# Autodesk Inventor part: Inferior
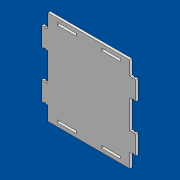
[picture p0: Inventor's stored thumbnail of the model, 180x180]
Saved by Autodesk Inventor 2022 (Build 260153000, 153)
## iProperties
Created: 2022-05
Part Number: Inferior
Material: Generic
Document SubType Name: Modeling
Designer: Daniel
Density: 1 g/cm^3
Appearance: Default
Author: Daniel
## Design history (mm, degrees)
sketch "Sketch1"
  geometry: L1 (60, -95)-(60, 5); L2 (-30, -95)-(-30, 5); L3 (-30, 5)-(-28.5, 5); L4 (60, -95)-(-30, -95); L5 (65, 0)-(65, 2.5); L6 (60, -45)-(49, -45); L7 (-34.1, -10)-(-35, -10); L8 (-35, -10)-(-35, -30); L9 (-34.1, -30)-(-35, -30); L10 (-34.1, -60)-(-35, -60); L11 (-35, -80)-(-35, -60); L12 (-34.1, -80)-(-35, -80); L13 (-30, 5)-(-30, -10); L14 (-30, -30)-(-30, -60); L15 (-30, -80)-(-30, -95); L16 (-35, 5)-(65, -95); L17 (-28.5, -88.5)-(58.5, -88.5); L18 (58.5, -88.5)-(58.5, -1.5); L19 (58.5, -1.5)-(-28.5, -1.5); L20 (-28.5, -1.5)-(-28.5, -88.5); L21 (-28.5, -88.5)-(58.5, -1.5); L22 (58.5, -88.5)-(-28.5, -1.5); L23 (-18.5, -1.5)-(-18.5, 1); L24 (-18.5, 1)-(1.5, 1); L25 (1.5, 1)-(1.5, -1.5); L26 (1.5, -1.5)-(-18.5, -1.5); L27 (28.5, -1.5)-(28.5, 1); L28 (28.5, 1)-(48.5, 1); L29 (48.5, 1)-(48.5, -1.5); L30 (48.5, -1.5)-(28.5, -1.5); L31 (15, -45)-(33.857, -45); L32 (58.5, -88.5)-(-28.5, -88.5); L33 (1.5, -88.5)-(-18.5, -88.5); L34 (-18.5, -88.5)-(-18.5, -91); L35 (-18.5, -91)-(1.5, -91); L36 (1.5, -91)-(1.5, -88.5); L37 (48.5, -88.5)-(28.5, -88.5); L38 (28.5, -88.5)-(28.5, -91); L39 (28.5, -91)-(48.5, -91); L40 (48.5, -91)-(48.5, -88.5); L41 (-28.5, -10)-(-31.8, -10); L42 (-31.8, -10)-(-35, -10); L43 (-35, -30)-(-28.5, -30); L44 (-28.5, -10)-(-28.5, 5); L45 (-28.5, 5)-(60, 5); L46 (-28.5, -30)-(-31.8, -30); L47 (-35, -80)-(-28.5, -80); L48 (-35, -60)-(-28.5, -60); L49 (-28.5, -60)-(-31.8, -60); L50 (-28.5, -80)-(-31.8, -80); L51 (-28.5, -95)-(-28.5, -80); L52 (-28.5, -60)-(-28.5, -30); L53 (-28.5, -10)-(-28.5, 5); L54 (15, -45)-(15, -32.026); L55 (58.5, -10)-(61.8, -10); L56 (61.8, -10)-(65, -10); L57 (65, -10)-(65, -30); L58 (64.1, -30)-(65, -30); L59 (65, -30)-(58.5, -30); L60 (58.5, -1.5)-(58.5, -88.5); L61 (58.5, -60)-(58.5, -30); L62 (58.5, -10)-(58.5, 5); L63 (65, -80)-(65, -60); L64 (65, -60)-(58.5, -60)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; C1 r 0.8 at (-31.8, -10); C2 r 0.8 at (-31.8, -30); C3 r 0.8 at (-31.8, -60); C4 r 0.8 at (-31.8, -80); C5 r 0.8 at (61.8, -10); C6 r 0.8 at (61.8, -30); C7 r 0.8 at (61.8, -60); C8 r 0.8 at (61.8, -80); 34 further points
  constraints: 132 end point, 26 symmetric about line, 23 point on line, 14 perpendicular, 8 centre point, 6 collinear, 5 coincident, 5 horizontal, 4 midpoint, 4 parallel, 1 vertical, 4 other
  dimensions: "d6" = 100 distance between parallel lines of L4 L3; "d8" = 87 distance of L19.end L18.end; "d10" = 2.5 distance of L23.start L23.end; "d11" = 2.5 distance of L27.start L27.end; "d12" = 3.3 distance of L41.start L41.end; "d13" = 1.6 diameter of C1; "d14" = 3.3 distance of L43.end L46.end; "d15" = 1.6 diameter of C2; "d17" = 3.3 distance of L48.end L49.end; "d18" = 3.3 distance of L47.end L50.end; "d19" = 1.6 diameter of C3; "d20" = 1.6 diameter of C4; "d23" = 27 distance between parallel lines of L27 L25; "d24" = 10 distance between parallel lines of L44 L23; "d25" = 10 distance between parallel lines of L62 L29; "d27" = 20 distance between parallel lines of L25 L23
extrude "Extrusion1" new body sketch "Sketch1" distance "d21" = 2.5; taper "d22" = 0 deg
sketch "Sketch2"
  geometry: C1 r 14.5 at (33.214, -26.786) reference; C2 r 14.5 at (33.214, -63.214) reference; C3 r 14.5 at (-3.214, -63.214) reference; C4 r 14.5 at (-3.214, -26.786) reference; C5 r 6.5 at (33.214, -63.214); C6 r 6.5 at (-3.214, -63.214); C7 r 6.5 at (-3.214, -26.786); C8 r 6.5 at (33.214, -26.786); 1 further point
  constraints: 4 centre point, 4 coincident
  dimensions: "d28" = 13 diameter of C5; "d29" = 13 diameter of C6; "d30" = 13 diameter of C7; "d31" = 13 diameter of C8
extrude "Extrusion2" cut sketch "Sketch2" distance "d32" = 10; taper "d33" = 0 deg
sketch "Boceto3"
  geometry: L1 (-35, -30)-(-32.6, -30) reference; L2 (-31, -30)-(-28.5, -30) reference; L3 (-28.5, -30)-(-28.5, -60) reference; L4 (-28.5, -60)-(-31, -60) reference; L5 (-32.6, -60)-(-35, -60) reference; L6 (-35, -60)-(-35, -80) reference; L7 (-35, -80)-(-32.6, -80) reference; L8 (-31, -80)-(-28.5, -80) reference; L9 (-28.5, -80)-(-28.5, -95) reference; L10 (-28.5, -95)-(58.5, -95) reference; L11 (58.5, -95)-(58.5, -80) reference; L12 (58.5, -80)-(61, -80) reference; L13 (62.6, -80)-(65, -80) reference; L14 (65, -80)-(65, -60) reference; L15 (65, -60)-(62.6, -60) reference; L16 (61, -60)-(58.5, -60) reference; L17 (58.5, -60)-(58.5, -30) reference; L18 (58.5, -30)-(61, -30) reference; L19 (62.6, -30)-(65, -30) reference; L20 (65, -30)-(65, -10) reference; L21 (65, -10)-(62.6, -10) reference; L22 (61, -10)-(58.5, -10) reference; L23 (58.5, -10)-(58.5, 5) reference; L24 (58.5, 5)-(-28.5, 5) reference; L25 (-28.5, 5)-(-28.5, -10) reference; L26 (-28.5, -10)-(-31, -10) reference; L27 (-32.6, -10)-(-35, -10) reference; L28 (-35, -10)-(-35, -30) reference; L29 (48.5, -88.5)-(48.5, -91) reference; L30 (48.5, -91)-(28.5, -91) reference; L31 (28.5, -91)-(28.5, -88.5) reference; L32 (28.5, -88.5)-(48.5, -88.5) reference; L33 (1.5, -88.5)-(1.5, -91) reference; L34 (1.5, -91)-(-18.5, -91) reference; L35 (-18.5, -91)-(-18.5, -88.5) reference; L36 (-18.5, -88.5)-(1.5, -88.5) reference; L37 (28.5, -1.5)-(28.5, 1) reference; L38 (28.5, 1)-(48.5, 1) reference; L39 (48.5, 1)-(48.5, -1.5) reference; L40 (48.5, -1.5)-(28.5, -1.5) reference; L41 (-18.5, -1.5)-(-18.5, 1) reference; L42 (-18.5, 1)-(1.5, 1) reference; L43 (1.5, 1)-(1.5, -1.5) reference; L44 (1.5, -1.5)-(-18.5, -1.5) reference; C1 r 6.5 at (-3.214, -26.786) reference; C2 r 6.5 at (33.214, -26.786) reference; C3 r 6.5 at (-3.214, -63.214) reference; C4 r 6.5 at (33.214, -63.214) reference; A1 r 0.8 centre (-31.8, -30) between (-31, -30) and (-32.6, -30) reference; A2 r 0.8 centre (-31.8, -60) between (-32.6, -60) and (-31, -60) reference; A3 r 0.8 centre (-31.8, -80) between (-31, -80) and (-32.6, -80) reference; A4 r 0.8 centre (61.8, -80) between (62.6, -80) and (61, -80) reference; A5 r 0.8 centre (61.8, -60) between (61, -60) and (62.6, -60) reference; A6 r 0.8 centre (61.8, -30) between (62.6, -30) and (61, -30) reference; A7 r 0.8 centre (61.8, -10) between (61, -10) and (62.6, -10) reference; A8 r 0.8 centre (-31.8, -10) between (-32.6, -10) and (-31, -10) reference; 1 further point
extrude "Extrusión3" join sketch "Boceto3" distance "d34" = 2.5; taper "d35" = 0 deg
sketch "Boceto4" dims "d36" = 25
  geometry: L1 (-35, -30)-(-32.6, -30) reference; L2 (-31, -30)-(-28.5, -30) reference; L3 (-28.5, -30)-(-28.5, -60) reference; L4 (-28.5, -60)-(-31, -60) reference; L5 (-32.6, -60)-(-35, -60) reference; L6 (-35, -60)-(-35, -80) reference; L7 (-35, -80)-(-32.6, -80) reference; L8 (-31, -80)-(-28.5, -80) reference; L9 (-28.5, -80)-(-28.5, -95) reference; L10 (-28.5, -95)-(58.5, -95) reference; L11 (58.5, -95)-(58.5, -80) reference; L12 (58.5, -80)-(61, -80) reference; L13 (62.6, -80)-(65, -80) reference; L14 (65, -80)-(65, -60) reference; L15 (65, -60)-(62.6, -60) reference; L16 (61, -60)-(58.5, -60) reference; L17 (58.5, -60)-(58.5, -30) reference; L18 (58.5, -30)-(61, -30) reference; L19 (62.6, -30)-(65, -30) reference; L20 (65, -30)-(65, -10) reference; L21 (65, -10)-(62.6, -10) reference; L22 (61, -10)-(58.5, -10) reference; L23 (58.5, -10)-(58.5, 5) reference; L24 (58.5, 5)-(-28.5, 5) reference; L25 (-28.5, 5)-(-28.5, -10) reference; L26 (-28.5, -10)-(-31, -10) reference; L27 (-32.6, -10)-(-35, -10) reference; L28 (-35, -10)-(-35, -30) reference; L29 (48.5, -88.5)-(48.5, -91) reference; L30 (48.5, -91)-(28.5, -91) reference; L31 (28.5, -91)-(28.5, -88.5) reference; L32 (28.5, -88.5)-(48.5, -88.5) reference; L33 (1.5, -88.5)-(1.5, -91) reference; L34 (1.5, -91)-(-18.5, -91) reference; L35 (-18.5, -91)-(-18.5, -88.5) reference; L36 (-18.5, -88.5)-(1.5, -88.5) reference; L37 (28.5, -1.5)-(28.5, 1) reference; L38 (28.5, 1)-(48.5, 1) reference; L39 (48.5, 1)-(48.5, -1.5) reference; L40 (48.5, -1.5)-(28.5, -1.5) reference; L41 (-18.5, -1.5)-(-18.5, 1) reference; L42 (-18.5, 1)-(1.5, 1) reference; L43 (1.5, 1)-(1.5, -1.5) reference; L44 (1.5, -1.5)-(-18.5, -1.5) reference; L45 (58.5, -88.5)-(-28.5, -88.5); L46 (-28.5, -88.5)-(-28.5, -1.5); L47 (-28.5, -1.5)-(58.5, -1.5); L48 (58.5, -1.5)-(58.5, -88.5); L49 (58.5, -88.5)-(-28.5, -1.5); L50 (58.5, -1.5)-(-28.5, -88.5); L51 (-28.5, -1.5)-(58.5, -88.5); L52 (-28.5, -88.5)-(58.5, -1.5); C1 r 1.5 at (23.839, -53.839); C2 r 1.5 at (23.839, -36.161); C3 r 1.5 at (6.161, -36.161); C4 r 1.5 at (6.161, -53.839); A1 r 0.8 centre (-31.8, -30) between (-31, -30) and (-32.6, -30) reference; A2 r 0.8 centre (-31.8, -60) between (-32.6, -60) and (-31, -60) reference; A3 r 0.8 centre (-31.8, -80) between (-31, -80) and (-32.6, -80) reference; A4 r 0.8 centre (61.8, -80) between (62.6, -80) and (61, -80) reference; A5 r 0.8 centre (61.8, -60) between (61, -60) and (62.6, -60) reference; A6 r 0.8 centre (61.8, -30) between (62.6, -30) and (61, -30) reference; A7 r 0.8 centre (61.8, -10) between (61, -10) and (62.6, -10) reference; A8 r 0.8 centre (-31.8, -10) between (-32.6, -10) and (-31, -10) reference; 5 further points
  constraints: 16 end point, 7 point on line, 4 centre point, 2 coincident, 2 parallel, 1 horizontal, 1 midpoint, 1 perpendicular, 26 other
  dimensions: "d37" = 3 diameter of C1; "d40" = 360 deg dimension on point (15, -45) L45.start (derived)
extrude "Extrusión4" cut sketch "Boceto4" distance "d42" = 2.5; taper "d43" = 0 deg
sketch "Boceto5"
  geometry: L1 (-35, -30)-(-32.6, -30) reference; L2 (-31, -30)-(-28.5, -30) reference; L3 (-28.5, -30)-(-28.5, -60) reference; L4 (-28.5, -60)-(-31, -60) reference; L5 (-32.6, -60)-(-35, -60) reference; L6 (-35, -60)-(-35, -80) reference; L7 (-35, -80)-(-32.6, -80) reference; L8 (-31, -80)-(-28.5, -80) reference; L9 (-28.5, -80)-(-28.5, -95) reference; L10 (-28.5, -95)-(58.5, -95) reference; L11 (58.5, -95)-(58.5, -80) reference; L12 (58.5, -80)-(61, -80) reference; L13 (62.6, -80)-(65, -80) reference; L14 (65, -80)-(65, -60) reference; L15 (65, -60)-(62.6, -60) reference; L16 (61, -60)-(58.5, -60) reference; L17 (58.5, -60)-(58.5, -30) reference; L18 (58.5, -30)-(61, -30) reference; L19 (62.6, -30)-(65, -30) reference; L20 (65, -30)-(65, -10) reference; L21 (65, -10)-(62.6, -10) reference; L22 (61, -10)-(58.5, -10) reference; L23 (58.5, -10)-(58.5, 5) reference; L24 (58.5, 5)-(-28.5, 5) reference; L25 (-28.5, 5)-(-28.5, -10) reference; L26 (-28.5, -10)-(-31, -10) reference; L27 (-32.6, -10)-(-35, -10) reference; L28 (-35, -10)-(-35, -30) reference; L29 (48.5, -88.5)-(48.5, -91) reference; L30 (48.5, -91)-(28.5, -91) reference; L31 (28.5, -91)-(28.5, -88.5) reference; L32 (28.5, -88.5)-(48.5, -88.5) reference; L33 (1.5, -88.5)-(1.5, -91) reference; L34 (1.5, -91)-(-18.5, -91) reference; L35 (-18.5, -91)-(-18.5, -88.5) reference; L36 (-18.5, -88.5)-(1.5, -88.5) reference; L37 (28.5, -1.5)-(28.5, 1) reference; L38 (28.5, 1)-(48.5, 1) reference; L39 (48.5, 1)-(48.5, -1.5) reference; L40 (48.5, -1.5)-(28.5, -1.5) reference; L41 (-18.5, -1.5)-(-18.5, 1) reference; L42 (-18.5, 1)-(1.5, 1) reference; L43 (1.5, 1)-(1.5, -1.5) reference; L44 (1.5, -1.5)-(-18.5, -1.5) reference; L45 (6.161, -53.839)-(58.5, -53.839); L46 (6.161, -36.161)-(58.5, -36.161); L47 (58.5, -53.839)-(48.5, -53.839); L48 (58.5, -36.161)-(48.5, -36.161); C1 r 1.5 at (23.839, -53.839) reference; C2 r 1.5 at (6.161, -36.161) reference; C3 r 1.5 at (23.839, -36.161) reference; C4 r 1.5 at (6.161, -53.839) reference; C5 r 2.25 at (48.5, -53.839); C6 r 2.25 at (48.5, -36.161); A1 r 0.8 centre (-31.8, -30) between (-31, -30) and (-32.6, -30) reference; A2 r 0.8 centre (-31.8, -60) between (-32.6, -60) and (-31, -60) reference; A3 r 0.8 centre (-31.8, -80) between (-31, -80) and (-32.6, -80) reference; A4 r 0.8 centre (61.8, -80) between (62.6, -80) and (61, -80) reference; A5 r 0.8 centre (61.8, -60) between (61, -60) and (62.6, -60) reference; A6 r 0.8 centre (61.8, -30) between (62.6, -30) and (61, -30) reference; A7 r 0.8 centre (61.8, -10) between (61, -10) and (62.6, -10) reference; A8 r 0.8 centre (-31.8, -10) between (-32.6, -10) and (-31, -10) reference; 1 further point
  constraints: 8 end point, 4 point on line, 2 centre point, 2 coincident, 2 perpendicular
  dimensions: "d44" = 10 distance of L45.end L47.end; "d45" = 10 distance of L46.end L48.end; "d46" = 4.5 diameter of C5; "d47" = 4.5 diameter of C6
extrude "Extrusión5" cut sketch "Boceto5" distance "d48" = 2.5; taper "d49" = 0 deg
body "Solid1"
node "Reference1"
node "Reference2"
node "Reference3"
node "Reference4"
node "Contorno proyectado1"
node "Contorno proyectado2"
node "Contorno proyectado3"
